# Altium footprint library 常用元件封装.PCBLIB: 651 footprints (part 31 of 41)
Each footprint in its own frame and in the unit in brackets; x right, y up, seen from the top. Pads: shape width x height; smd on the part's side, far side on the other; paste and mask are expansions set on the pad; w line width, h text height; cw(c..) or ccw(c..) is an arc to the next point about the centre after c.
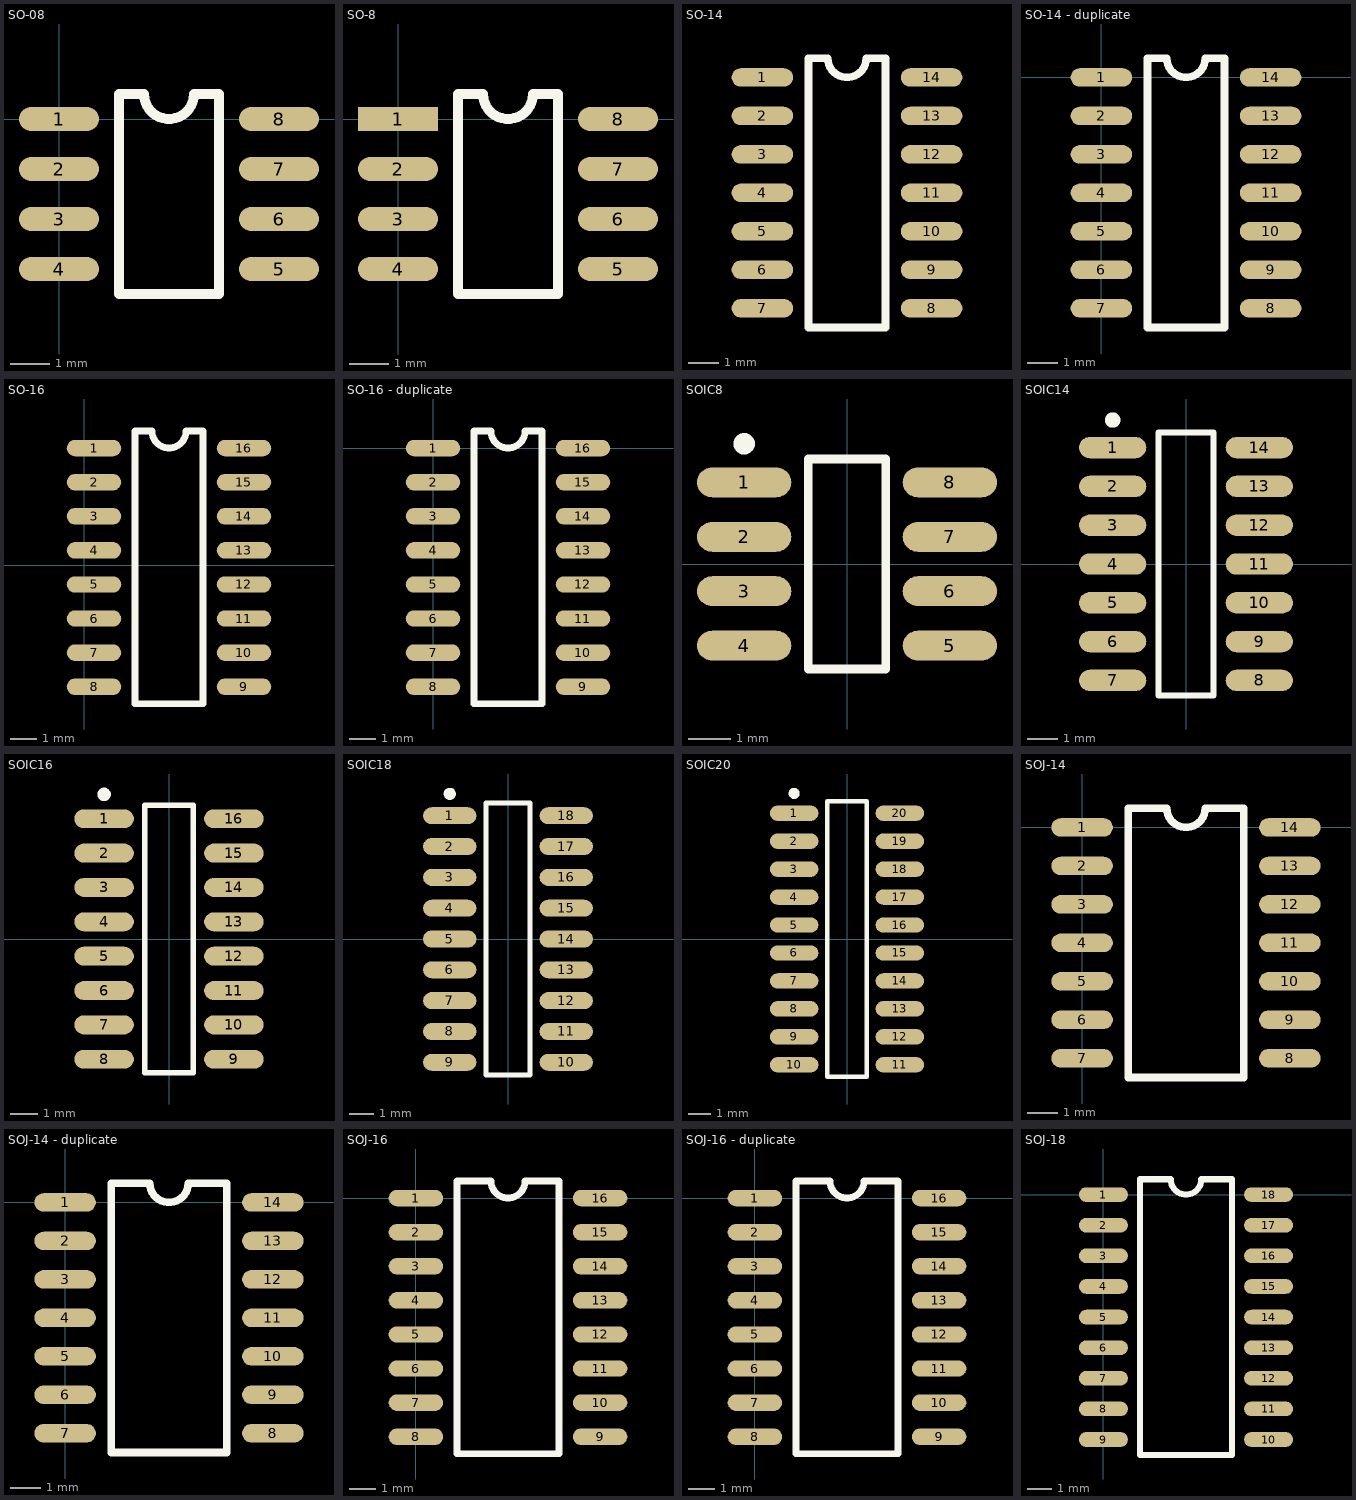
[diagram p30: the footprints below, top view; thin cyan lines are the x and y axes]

## SO-08 [mil]
pads (8):
  oval 80x24 smd: 1(0,0) 2(0,-50) 3(0,-100) 4(0,-150) 5(220,-150) 6(220,-100) 7(220,-50) 8(220,0)
TopOverlay:
  lines w10: 60,-175 60,25 85,25 ccw(c110,25) 135,25 160,25 160,-175 60,-175

## SO-8 [mil]
pads (8):
  rect 80x24 smd: 1(0,0)
  oval 80x24 smd: 2(0,-50) 3(0,-100) 4(0,-150) 5(220,-150) 6(220,-100) 7(220,-50) 8(220,0)
TopOverlay:
  lines w10: 60,-175 160,-175 160,25 135,25 cw(c110,25) 85,25 60,25 60,-175

## SO-14 [mil]
pads (14):
  oval 80x24 smd: 1(142,-76) 2(142,-126) 3(142,-176) 4(142,-226) 5(142,-276) 6(142,-326) 7(142,-376) 8(362,-376) 9(362,-326) 10(362,-276) 11(362,-226) 12(362,-176) 13(362,-126) 14(362,-76)
TopOverlay:
  lines w10: 202,-401 202,-51 227,-51 ccw(c252,-51) 277,-51 302,-51 302,-401 202,-401

## SO-14 - duplicate [mil]
pads (14):
  oval 80x24 smd: 1(0,0) 2(0,-50) 3(0,-100) 4(0,-150) 5(0,-200) 6(0,-250) 7(0,-300) 8(220,-300) 9(220,-250) 10(220,-200) 11(220,-150) 12(220,-100) 13(220,-50) 14(220,0)
TopOverlay:
  lines w10: 60,-325 60,25 85,25 ccw(c110,25) 135,25 160,25 160,-325 60,-325

## SO-16 [mil]
pads (16):
  oval 80x24 smd: 1(14,172) 2(14,122) 3(14,72) 4(14,22) 5(14,-28) 6(14,-78) 7(14,-128) 8(14,-178) 9(234,-178) 10(234,-128) 11(234,-78) 12(234,-28) 13(234,22) 14(234,72) 15(234,122) 16(234,172)
TopOverlay:
  lines w10: 74,-203 174,-203 174,197 149,197 cw(c124,197) 99,197 74,197 74,-203

## SO-16 - duplicate [mil]
pads (16):
  oval 80x24 smd: 1(0,0) 2(0,-50) 3(0,-100) 4(0,-150) 5(0,-200) 6(0,-250) 7(0,-300) 8(0,-350) 9(220,-350) 10(220,-300) 11(220,-250) 12(220,-200) 13(220,-150) 14(220,-100) 15(220,-50) 16(220,0)
TopOverlay:
  lines w10: 60,-375 160,-375 160,25 135,25 cw(c110,25) 85,25 60,25 60,-375

## SOIC8 [mm]
height 1.55
pads (8):
  oval 2.2x0.7 smd: 1(-2.4,1.905) 2(-2.4,0.635) 3(-2.4,-0.635) 4(-2.4,-1.905) 5(2.4,-1.905) 6(2.4,-0.635) 7(2.4,0.635) 8(2.4,1.905)
TopOverlay:
  circle w0.25: c-2.4,2.805 r0.125
  lines w0.2: -0.9,-2.45 -0.9,2.45 0.9,2.45 0.9,-2.45 -0.9,-2.45

## SOIC14 [mm]
height 1.55
pads (14):
  oval 2.2x0.7 smd: 1(-2.4,3.81) 2(-2.4,2.54) 3(-2.4,1.27) 4(-2.4,0) 5(-2.4,-1.27) 6(-2.4,-2.54) 7(-2.4,-3.81) 8(2.4,-3.81) 9(2.4,-2.54) 10(2.4,-1.27) 11(2.4,0) 12(2.4,1.27) 13(2.4,2.54) 14(2.4,3.81)
TopOverlay:
  circle w0.25: c-2.4,4.71 r0.125
  lines w0.2: -0.9,-4.3 0.9,-4.3 0.9,4.3 -0.9,4.3 -0.9,-4.3

## SOIC16 [mm]
height 1.55
pads (16):
  oval 2.2x0.7 smd: 1(-2.4,4.445) 2(-2.4,3.175) 3(-2.4,1.905) 4(-2.4,0.635) 5(-2.4,-0.635) 6(-2.4,-1.905) 7(-2.4,-3.175) 8(-2.4,-4.445) 9(2.4,-4.445) 10(2.4,-3.175) 11(2.4,-1.905) 12(2.4,-0.635) 13(2.4,0.635) 14(2.4,1.905) 15(2.4,3.175) 16(2.4,4.445)
TopOverlay:
  circle w0.25: c-2.4,5.345 r0.125
  lines w0.2: -0.9,-4.95 -0.9,4.95 0.9,4.95 0.9,-4.95 -0.9,-4.95

## SOIC18 [mm]
height 1.55
pads (18):
  oval 2.2x0.7 smd: 1(-2.4,5.08) 2(-2.4,3.81) 3(-2.4,2.54) 4(-2.4,1.27) 5(-2.4,0) 6(-2.4,-1.27) 7(-2.4,-2.54) 8(-2.4,-3.81) 9(-2.4,-5.08) 10(2.4,-5.08) 11(2.4,-3.81) 12(2.4,-2.54) 13(2.4,-1.27) 14(2.4,0) 15(2.4,1.27) 16(2.4,2.54) 17(2.4,3.81) 18(2.4,5.08)
TopOverlay:
  circle w0.25: c-2.4,5.98 r0.125
  lines w0.2: -0.9,-5.6 0.9,-5.6 0.9,5.6 -0.9,5.6 -0.9,-5.6

## SOIC20 [mm]
height 1.55
pads (20):
  oval 2.2x0.7 smd: 1(-2.4,5.715) 2(-2.4,4.445) 3(-2.4,3.175) 4(-2.4,1.905) 5(-2.4,0.635) 6(-2.4,-0.635) 7(-2.4,-1.905) 8(-2.4,-3.175) 9(-2.4,-4.445) 10(-2.4,-5.715) 11(2.4,-5.715) 12(2.4,-4.445) 13(2.4,-3.175) 14(2.4,-1.905) 15(2.4,-0.635) 16(2.4,0.635) 17(2.4,1.905) 18(2.4,3.175) 19(2.4,4.445) 20(2.4,5.715)
TopOverlay:
  circle w0.25: c-2.4,6.615 r0.125
  lines w0.2: -0.9,-6.25 0.9,-6.25 0.9,6.25 -0.9,6.25 -0.9,-6.25

## SOJ-14 [mil]
pads (14):
  oval 80x24 smd: 1(0,0) 2(0,-50) 3(0,-100) 4(0,-150) 5(0,-200) 6(0,-250) 7(0,-300) 8(270,-300) 9(270,-250) 10(270,-200) 11(270,-150) 12(270,-100) 13(270,-50) 14(270,0)
TopOverlay:
  lines w10: 60,-325 210,-325 210,25 160,25 cw(c135,25) 110,25 60,25 60,-325

## SOJ-14 - duplicate [mil]
pads (14):
  oval 80x24 smd: 1(0,0) 2(0,-50) 3(0,-100) 4(0,-150) 5(0,-200) 6(0,-250) 7(0,-300) 8(270,-300) 9(270,-250) 10(270,-200) 11(270,-150) 12(270,-100) 13(270,-50) 14(270,0)
TopOverlay:
  lines w10: 60,-325 60,25 110,25 ccw(c135,25) 160,25 210,25 210,-325 60,-325

## SOJ-16 [mil]
pads (16):
  oval 80x24 smd: 1(0,0) 2(0,-50) 3(0,-100) 4(0,-150) 5(0,-200) 6(0,-250) 7(0,-300) 8(0,-350) 9(270,-350) 10(270,-300) 11(270,-250) 12(270,-200) 13(270,-150) 14(270,-100) 15(270,-50) 16(270,0)
TopOverlay:
  lines w10: 60,-375 60,25 110,25 ccw(c135,25) 160,25 210,25 210,-375 60,-375

## SOJ-16 - duplicate [mil]
pads (16):
  oval 80x24 smd: 1(0,0) 2(0,-50) 3(0,-100) 4(0,-150) 5(0,-200) 6(0,-250) 7(0,-300) 8(0,-350) 9(270,-350) 10(270,-300) 11(270,-250) 12(270,-200) 13(270,-150) 14(270,-100) 15(270,-50) 16(270,0)
TopOverlay:
  lines w10: 60,-375 60,25 110,25 ccw(c135,25) 160,25 210,25 210,-375 60,-375

## SOJ-18 [mil]
pads (18):
  oval 80x24 smd: 1(0,0) 2(0,-50) 3(0,-100) 4(0,-150) 5(0,-200) 6(0,-250) 7(0,-300) 8(0,-350) 9(0,-400) 10(270,-400) 11(270,-350) 12(270,-300) 13(270,-250) 14(270,-200) 15(270,-150) 16(270,-100) 17(270,-50) 18(270,0)
TopOverlay:
  lines w10: 60,-425 60,25 110,25 ccw(c135,25) 160,25 210,25 210,-425 60,-425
